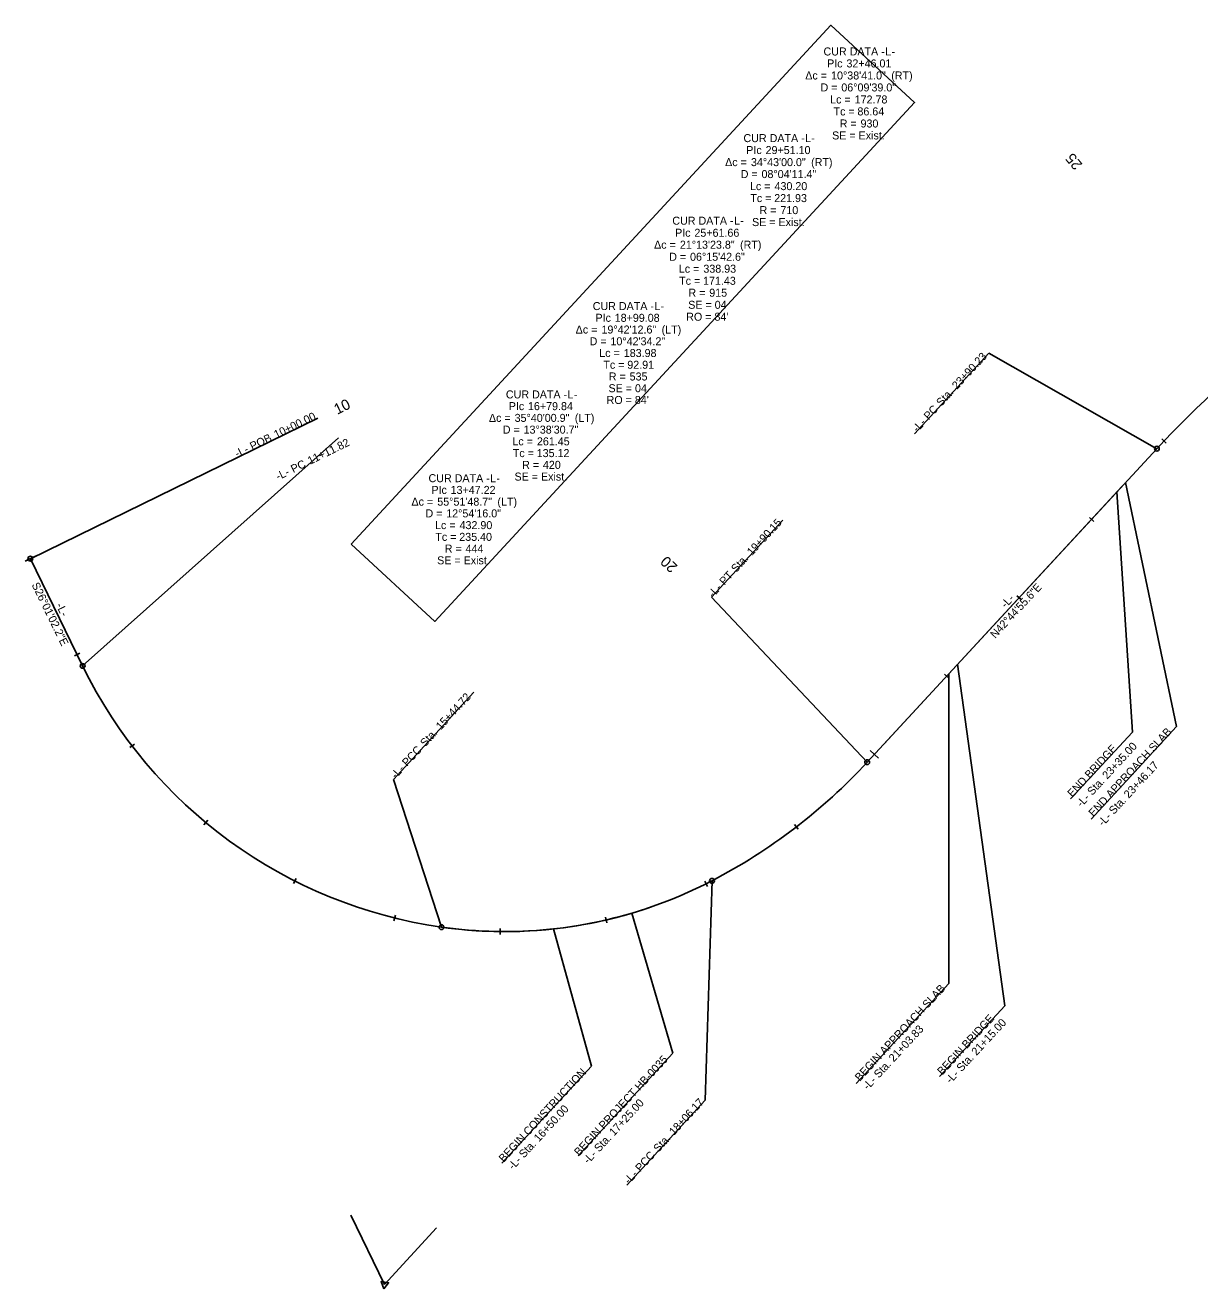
# Model space of a CAD drawing. Extents: x 1768031 to 1770464, y 999587 to 1004918.
# Drawn here: x 1768031 to 1769132, y 999587 to 1000771 of the extents above; entities that cross this region are included whole.
import ezdxf

# ---------------------------------------------------------------- set-up
doc = ezdxf.new("R2010")
doc.units = 0
for name, color, linetype in [('Default', 7, 'Continuous'), ('P_NCDOT_Approach_Slab', 7, 'Continuous'), ('P_NCDOT_SS_Fill_Text', 7, 'Continuous'), ('P_RDY_DGN_Element_Guardrail', 7, 'Continuous'), ('P_RDY_Dimension', 7, 'Continuous'), ('P_RDY_Dimension_Text', 7, 'Continuous'), ('P_RDY_DSN_Text', 7, 'Continuous'), ('P_RDY_Limits_of_Construction', 7, 'Continuous'), ('P_RDY_Slope_Stake_Cut_Text', 7, 'Continuous'), ('P_RDY_Terminator_Cell', 7, 'Continuous'), ('Typical_Arrow_Superelevation_CELL', 7, 'Continuous')]:
    doc.layers.add(name, color=color, linetype=linetype)

msp = doc.modelspace()

# ---------------------------------------------------------------- linework, layer by layer
at = {"layer": 'Default'}
for q in [(1768336.5, 999655.6), (1768416.9, 999643.8), (1768368, 999590.9)]:
    msp.add_line((1768368, 999590.9), q, dxfattribs=at)
msp.add_lwpolyline([(1768367.4, 999586.8), (1768371.9, 999592.4), (1768364.8, 999593.5)], close=True, dxfattribs=at)
at = {"layer": 'P_NCDOT_Approach_Slab'}
msp.add_lwpolyline([(1768336.9, 1000284.5), (1768786.5, 1000770.9), (1768864.8, 1000698.6), (1768415.2, 1000212.2)], close=True, dxfattribs=at)
at = {"layer": 'P_RDY_DGN_Element_Guardrail'}
for centre in [(1769092, 1000374.1), (1768820.4, 1000080.3), (1768421.4, 999925.7)]:
    msp.add_circle(centre, 0.05, dxfattribs=at)
at = {"layer": 'P_RDY_Dimension'}
for p, q in [((1768040.9, 1000273.4), (1768031.3, 1000268.7)), ((1768823.2, 1000091.2), (1768831, 1000084))]:
    msp.add_line(p, q, dxfattribs=at)
at = {"layer": 'P_RDY_DSN_Text'}
for p, q in [((1768820.4, 1000080.3), (1769092, 1000374.1)), ((1768036.1, 1000271), (1768085.1, 1000170.5))]:
    msp.add_line(p, q, dxfattribs=at)
for centre, radius, start, end in [((1769763.9, 999753), 915, 116.0279, 137.2512), ((1768484.1, 1000365.3), 444, 206.0173, 261.8808), ((1768427.6, 1000443.5), 535, 297.5477, 317.2512), ((1768480.7, 1000341.5), 420, 261.8808, 297.5477)]:
    msp.add_arc(centre, radius, start, end, dxfattribs=at)
at = {"layer": 'P_RDY_Limits_of_Construction'}
msp.add_line((1768836.2, 1000097.4), (1769059.2, 1000338.6), dxfattribs=at)
for centre, radius, start, end in [((1769763.9, 999753), 915, 116.0279, 137.2512), ((1768427.6, 1000443.5), 535, 297.5477, 317.2512)]:
    msp.add_arc(centre, radius, start, end, dxfattribs=at)
at = {"layer": 'P_RDY_Slope_Stake_Cut_Text'}
for p, q in [((1768934.6, 1000463.5), (1768864.9, 1000388)), ((1769092, 1000374.1), (1768934.6, 1000463.5)), ((1768036.1, 1000271), (1768305.7, 1000402.6)), ((1768036.1, 1000271), (1768305.7, 1000402.6)), ((1768085.1, 1000170.5), (1768324.9, 1000384.4)), ((1769062.7, 1000342.4), (1769110.5, 1000113.7)), ((1769054.5, 1000333.6), (1769069, 1000108.5)), ((1768674.5, 1000235), (1768741.4, 1000307.1)), ((1768820.4, 1000080.3), (1768674.5, 1000235)), ((1768897, 999872.8), (1768897, 1000163.2)), ((1768949.4, 999851.8), (1768905.2, 1000172)), ((1768376.4, 1000064.1), (1768451.9, 1000145.8)), ((1769069, 1000108.5), (1769011.1, 1000045.9)), ((1769110.5, 1000113.7), (1769030.4, 1000027)), ((1768421.4, 999925.7), (1768376.4, 1000064.1)), ((1768675, 999969.1), (1768668.5, 999763.4)), ((1768638.3, 999807.5), (1768599.9, 999938.8)), ((1768561.9, 999795.5), (1768526.4, 999924)), ((1768810.2, 999779), (1768897, 999872.8)), ((1768888.3, 999785.8), (1768949.4, 999851.8)), ((1768549.4, 999711.4), (1768638.3, 999807.5)), ((1768477.9, 999704.5), (1768561.9, 999795.5)), ((1768595.1, 999684), (1768668.5, 999763.4))]:
    msp.add_line(p, q, dxfattribs=at)
for centre in [(1769092, 1000374.1), (1768036.1, 1000271), (1768036.1, 1000271), (1768085.1, 1000170.5), (1768820.4, 1000080.3), (1768675, 999969.1), (1768421.4, 999925.7)]:
    msp.add_circle(centre, 2.25, dxfattribs=at)
at = {"layer": 'P_RDY_Terminator_Cell'}
for p, q in [((1769096.7, 1000383.2), (1769100.7, 1000379.4)), ((1769028.7, 1000309.7), (1769032.8, 1000306)), ((1768960.8, 1000236.3), (1768964.9, 1000232.6)), ((1768082.4, 1000182.4), (1768077.5, 1000179.9)), ((1768893, 1000162.9), (1768897, 1000159.1)), ((1768133.6, 1000097.3), (1768129.2, 1000093.9)), ((1768202.3, 1000025.8), (1768198.8, 1000021.5)), ((1768752.3, 1000021.8), (1768755.6, 1000017.4)), ((1768285.2, 999971.4), (1768282.7, 999966.5)), ((1768668.3, 999968.8), (1768670.7, 999963.9)), ((1768378.2, 999936.9), (1768376.9, 999931.6)), ((1768575.1, 999935.1), (1768576.3, 999929.7)), ((1768476.5, 999924.3), (1768476.5, 999918.8))]:
    msp.add_line(p, q, dxfattribs=at)
at = {"layer": 'Typical_Arrow_Superelevation_CELL'}
msp.add_arc((1768480.7, 1000341.5), 420, 261.8808, 289.7166, dxfattribs=at)

# ---------------------------------------------------------------- texts
at = {"layer": 'P_NCDOT_Approach_Slab'}
for s, p in [('CUR DATA -', (1768779.5, 1000742.6)), ('L', (1768837.4, 1000742.6)), ('-', (1768843.2, 1000742.6)), ('PIc ', (1768782.9, 1000731.4)), ('32+46.01', (1768801, 1000731.4)), ('Δc = ', (1768762.4, 1000720.1)), ('10°38\'41.0"', (1768786.6, 1000720.1)), (' (RT)', (1768840.2, 1000720.1)), ('D = ', (1768776.7, 1000708.9)), ('06°09\'39.0"', (1768796.2, 1000708.9)), ('Lc = ', (1768785.7, 1000697.6)), ('172.78', (1768808.7, 1000697.6)), ('86.64', (1768811.3, 1000686.4)), ('Tc = ', (1768788.9, 1000686.4)), ('R = ', (1768794.7, 1000675.1)), ('930', (1768814.2, 1000675.1)), ('SE = Exist.', (1768787.6, 1000663.9)), ('CUR DATA -', (1768704.5, 1000661.4)), ('L', (1768762.3, 1000661.4)), ('-', (1768768.1, 1000661.4)), ('PIc ', (1768707.1, 1000650.2)), ('29+51.10', (1768725.2, 1000650.2)), (' (RT)', (1768765.1, 1000638.9)), ('Δc = ', (1768687.3, 1000638.9)), ('D = ', (1768701.9, 1000627.7)), ('34°43\'00.0"', (1768711.5, 1000638.9)), ('08°04\'11.4"', (1768721.4, 1000627.7)), ('Lc = ', (1768710.6, 1000616.4)), ('430.20', (1768733.6, 1000616.4)), ('Tc = ', (1768710.9, 1000605.2)), ('221.93', (1768733.3, 1000605.2)), ('R = ', (1768719.6, 1000593.9)), ('710', (1768739.1, 1000593.9)), ('CUR DATA -', (1768637.8, 1000584)), ('L', (1768695.6, 1000584)), ('SE = Exist.', (1768712.5, 1000582.7)), ('PIc ', (1768640.4, 1000572.7)), ('25+61.66', (1768658.5, 1000572.7)), ('-', (1768701.5, 1000584)), ('Δc = ', (1768620.7, 1000561.5)), ('21°13\'23.8"', (1768644.9, 1000561.5)), (' (RT)', (1768698.5, 1000561.5)), ('D = ', (1768634.9, 1000550.2)), ('06°15\'42.6"', (1768654.4, 1000550.2)), ('Lc = ', (1768643.9, 1000539)), ('338.93', (1768666.9, 1000539)), ('Tc = ', (1768644.2, 1000527.7)), ('171.43', (1768666.6, 1000527.7)), ('R = ', (1768652.9, 1000516.5)), ('915', (1768672.4, 1000516.5)), ('CUR DATA -', (1768563.2, 1000504)), ('L', (1768621, 1000504)), ('-', (1768626.8, 1000504)), ('SE = 04', (1768652.7, 1000505.2)), ('PIc ', (1768565.8, 1000493)), ('18+99.08', (1768583.8, 1000493)), ("RO = 84'", (1768650.8, 1000494)), ('Δc = ', (1768547.2, 1000482)), ('19°42\'12.6"', (1768571.4, 1000482)), (' (LT)', (1768625, 1000482)), ('D = ', (1768560.3, 1000471)), ('10°42\'34.2"', (1768579.8, 1000471)), ('Lc = ', (1768569.3, 1000460)), ('183.98', (1768592.3, 1000460)), ('Tc = ', (1768573.2, 1000449)), ('R = ', (1768578.3, 1000438)), ('92.91', (1768595.6, 1000449)), ('535', (1768597.8, 1000438)), ('SE = 04', (1768578, 1000427)), ('CUR DATA -', (1768481.8, 1000421.2)), ('L', (1768539.6, 1000421.2)), ('-', (1768545.5, 1000421.2)), ("RO = 84'", (1768576.2, 1000416)), ('PIc ', (1768484.5, 1000410.2)), ('16+79.84', (1768502.5, 1000410.2)), ('Δc = ', (1768465.9, 1000399.2)), ('35°40\'00.9"', (1768490, 1000399.2)), (' (LT)', (1768543.6, 1000399.2)), ('D = ', (1768478.9, 1000388.2)), ('13°38\'30.7"', (1768498.4, 1000388.2)), ('Lc = ', (1768487.9, 1000377.2)), ('261.45', (1768510.9, 1000377.2)), ('Tc = ', (1768488.3, 1000366.2)), ('R = ', (1768497, 1000355.2)), ('135.12', (1768510.7, 1000366.2)), ('420', (1768516.5, 1000355.2)), ('SE = Exist.', (1768489.9, 1000344.2)), ('CUR DATA -', (1768409.3, 1000342.7)), ('PIc ', (1768412, 1000331.7)), ('13+47.22', (1768430, 1000331.7)), ('L', (1768467.1, 1000342.7)), ('-', (1768472.9, 1000342.7)), ('Δc = ', (1768393.3, 1000320.7)), ('55°51\'48.7"', (1768417.5, 1000320.7)), (' (LT)', (1768471.1, 1000320.7)), ('D = ', (1768406.4, 1000309.7)), ('12°54\'16.0"', (1768425.9, 1000309.7)), ('Lc = ', (1768415.4, 1000298.7)), ('432.90', (1768438.4, 1000298.7)), ('Tc = ', (1768415.7, 1000287.7)), ('235.40', (1768438.1, 1000287.7)), ('R = ', (1768424.5, 1000276.7)), ('444', (1768444, 1000276.7)), ('SE = Exist.', (1768417.4, 1000265.7))]:
    msp.add_text(s, height=7.5, dxfattribs=at).set_placement(p)
at = {"layer": 'P_NCDOT_SS_Fill_Text'}
for s, rotation, p in [('S26°01\'02.2"E', 296.0173, (1768037.1, 1000246.6)), ('N42°44\'55.6"E', 47.2512, (1768940.4, 1000195.8)), ('L', 47.2512, (1768952.7, 1000226.7)), ('-', 47.2512, (1768956.6, 1000231)), ('L', 296.0173, (1768061.4, 1000224.2)), ('-', 296.0173, (1768059.9, 1000227.4)), ('-', 47.2512, (1768950.3, 1000224.2)), ('-', 296.0173, (1768064, 1000219))]:
    msp.add_text(s, height=7.5, rotation=rotation, dxfattribs=at).set_placement(p)
at = {"layer": 'P_RDY_Dimension_Text'}
for s, rotation, p in [('25', 129.6506, (1769022.7, 1000640.6)), ('10', 26.0173, (1768323.7, 1000405.8)), ('20', 137.2512, (1768643.4, 1000264.2))]:
    msp.add_text(s, height=10, rotation=rotation, dxfattribs=at).set_placement(p)
at = {"layer": 'P_RDY_Slope_Stake_Cut_Text'}
for s, rotation, p in [('23+90.23', 47.2512, (1768904.6, 1000429.1)), (' Sta. ', 47.2512, (1768888, 1000411.2)), ('PC', 47.2512, (1768878.1, 1000400.5)), ('10+00.00', 26.0173, (1768266.6, 1000383.5)), ('- ', 47.2512, (1768873.7, 1000395.8)), ('POB', 26.0173, (1768244.1, 1000372.5)), ('L', 47.2512, (1768869.8, 1000391.5)), ('-', 47.2512, (1768867.4, 1000389)), ('L', 26.0173, (1768233.1, 1000367.2)), ('11+11.82', 26.0173, (1768298.2, 1000358.9)), ('-', 26.0173, (1768230, 1000365.7)), ('- ', 26.0173, (1768238.4, 1000369.7)), ('PC', 26.0173, (1768282.5, 1000351.2)), ('L', 26.0173, (1768271.5, 1000345.8)), ('- ', 26.0173, (1768276.7, 1000348.4)), ('-', 26.0173, (1768268.3, 1000344.3)), ('19+90.15', 47.1775, (1768712.4, 1000273.4)), (' Sta. ', 47.1775, (1768695.7, 1000255.5)), ('PT', 47.1775, (1768686.6, 1000245.6)), ('- ', 47.1775, (1768682.3, 1000240.9)), ('L', 47.1775, (1768678.3, 1000236.7)), ('-', 47.1775, (1768676, 1000234.1)), ('15+44.72', 47.2512, (1768420.9, 1000110)), (' Sta. ', 47.2512, (1768404.3, 1000092.1)), ('END APPROACH SLAB', 47.2512, (1769032.6, 1000028.5)), ('PCC', 47.2512, (1768389.2, 1000075.8)), ('END BRIDGE', 47.2512, (1769012.8, 1000046.8)), ('-L- Sta. 23+35.00', 47.2512, (1769021.2, 1000037.6)), ('-L- Sta. 23+46.17', 47.2512, (1769041.4, 1000019.7)), ('L', 47.2512, (1768380.9, 1000066.8)), ('-', 47.2512, (1768378.6, 1000064.3)), ('- ', 47.2512, (1768384.9, 1000071.1)), ('BEGIN APPROACH SLAB', 47.1775, (1768813.6, 999780.7)), ('BEGIN BRIDGE', 47.1775, (1768890.8, 999786.4)), ('-L- Sta. 21+03.83', 47.1775, (1768821.1, 999772.6)), ('-L- Sta. 21+15.00', 47.1775, (1768898.6, 999778.6)), ('BEGIN PROJECT HB-0035', 47.2512, (1768550.5, 999710.7)), ('BEGIN CONSTRUCTION', 47.2512, (1768479.8, 999704.8)), ('-L- Sta. 16+50.00', 47.2512, (1768488.5, 999697.7)), ('-L- Sta. 17+25.00', 47.2512, (1768559, 999703.3)), ('18+06.17', 47.2512, (1768639.4, 999730.1)), (' Sta. ', 47.2512, (1768622.8, 999712.1)), ('PCC', 47.2512, (1768607.8, 999695.9)), ('L', 47.2512, (1768599.5, 999686.9)), ('-', 47.2512, (1768597.2, 999684.3)), ('- ', 47.2512, (1768603.5, 999691.2))]:
    msp.add_text(s, height=7.5, rotation=rotation, dxfattribs=at).set_placement(p)

doc.saveas('drawing.dxf')
